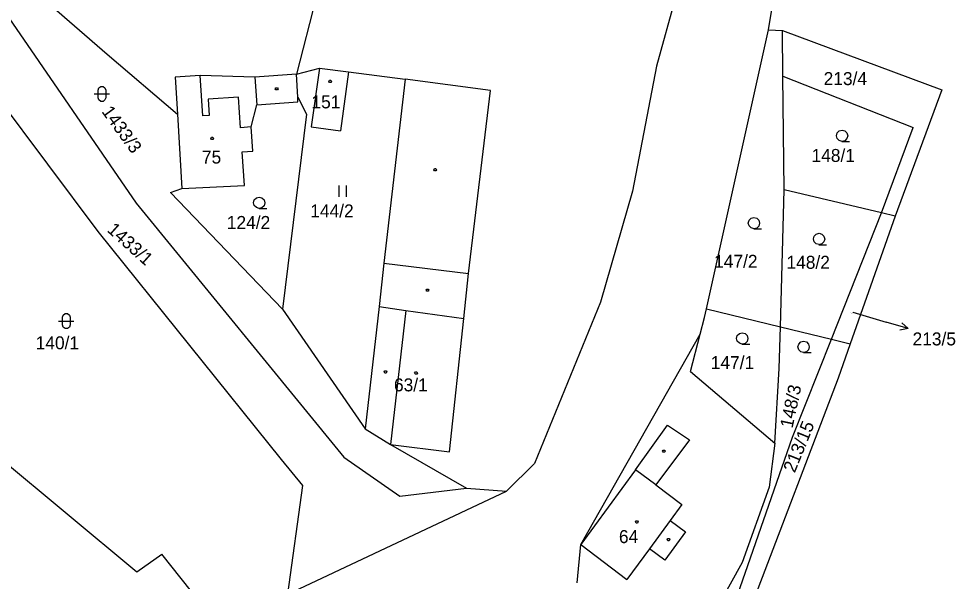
# Model space of a CAD drawing. Extents: x -852001 to -842497, y -1063614 to -1052182.
# Drawn here: x -849124.2 to -849001.5, y -1056168.6 to -1056094.9 of the extents above; entities that cross this region are included whole.
import ezdxf

# ---------------------------------------------------------------- set-up
doc = ezdxf.new("R2010")
doc.units = 0
for name, color, linetype in [('Default', 7, 'Continuous'), ('KN_HRANICE', 7, 'Continuous'), ('KN_KULTURY', 7, 'Continuous'), ('KN_PARCELY', 7, 'Continuous'), ('KN_SLUCKY', 7, 'Continuous')]:
    doc.layers.add(name, color=color, linetype=linetype)

# ---------------------------------------------------------------- blocks, each defined once
blk = doc.blocks.new('304')
at = {"layer": 'Default'}
blk.add_lwpolyline([(0, 0), (-0.38, 0.1), (-0.65, 0.37), (-0.75, 0.74), (-0.65, 1.11), (-0.38, 1.38), (-0.01, 1.48), (0.36, 1.38), (0.63, 1.11), (0.73, 0.73), (0.63, 0.35), (0.36, 0.08), (-0.02, -0.02), (0.98, -0.02)], dxfattribs=at)
blk = doc.blocks.new('306')
at = {"layer": 'Default'}
for p, q in [((-0.5, 1.5), (-0.5, 0)), ((0.5, 0), (0.5, 1.5))]:
    blk.add_line(p, q, dxfattribs=at)
blk = doc.blocks.new('316')
at = {"layer": 'Default'}
for points in [[(-0.5, 1.5), (-0.4, 1.79), (-0.15, 1.97), (0.16, 1.97), (0.41, 1.79), (0.51, 1.5), (0.51, 0.5), (0.41, 0.21), (0.16, 0.03), (-0.15, 0.03), (-0.4, 0.21), (-0.5, 0.5), (-0.5, 1.5)], [(-1, 1), (0.27, 1), (1, 1)]]:
    blk.add_lwpolyline(points, dxfattribs=at)
blk = doc.blocks.new('10292')
at = {"layer": 'Default'}
blk.add_line((0, 3), (0, 0), dxfattribs=at)
blk.add_lwpolyline([(-0.5, 2), (0, 3), (0.5, 2)], dxfattribs=at)
blk = doc.blocks.new('402')
at = {"layer": 'Default'}
blk.add_lwpolyline([(0.09, 0.15), (0.18, 0), (0.09, -0.15), (-0.09, -0.15), (-0.18, 0), (-0.09, 0.15), (0.09, 0.15)], dxfattribs=at)

msp = doc.modelspace()

# ---------------------------------------------------------------- linework, layer by layer
at = {"layer": 'KN_HRANICE'}
for p, q in [((-849061.59, -1055999.43), (-849087.8, -1056102.18)), ((-849061.59, -1055999.43), (-849087.8, -1056102.18)), ((-849026.02, -1056048.69), (-849040.65, -1056101.15)), ((-849026.02, -1056048.69), (-849040.65, -1056101.15)), ((-849025.96, -1056096.38), (-849019.75, -1056059.38)), ((-849025.96, -1056096.38), (-849019.75, -1056059.38)), ((-849120.52, -1056092.73), (-849112.59, -1056099.57)), ((-849120.52, -1056092.73), (-849112.59, -1056099.57)), ((-849125.98, -1056094.1), (-849108.8, -1056119.1)), ((-849125.98, -1056094.1), (-849108.8, -1056119.1)), ((-849113.79, -1056122.8), (-849134.65, -1056094.95)), ((-849113.79, -1056122.8), (-849134.65, -1056094.95)), ((-849034.09, -1056132.93), (-849025.96, -1056096.38)), ((-849034.09, -1056132.93), (-849025.96, -1056096.38)), ((-849025.96, -1056096.38), (-849024.15, -1056096.47)), ((-849025.96, -1056096.38), (-849024.15, -1056096.47)), ((-849024.15, -1056096.47), (-849003.24, -1056104.25)), ((-849024.08, -1056102.46), (-849024.15, -1056096.47)), ((-849024.15, -1056096.47), (-849003.24, -1056104.25)), ((-849024.08, -1056102.46), (-849024.15, -1056096.47)), ((-849112.59, -1056099.57), (-849103.4, -1056107.43)), ((-849112.59, -1056099.57), (-849103.4, -1056107.43)), ((-849087.8, -1056102.18), (-849084.8, -1056101.39)), ((-849087.8, -1056102.18), (-849084.8, -1056101.39)), ((-849084.8, -1056101.39), (-849085.87, -1056109.07)), ((-849084.8, -1056101.39), (-849085.87, -1056109.07)), ((-849084.8, -1056101.39), (-849081, -1056101.88)), ((-849084.8, -1056101.39), (-849081, -1056101.88)), ((-849040.65, -1056101.15), (-849043.77, -1056117.52)), ((-849040.65, -1056101.15), (-849043.77, -1056117.52)), ((-849100.4, -1056102.37), (-849103.68, -1056102.59)), ((-849100.4, -1056102.37), (-849103.68, -1056102.59)), ((-849103.68, -1056102.59), (-849103.4, -1056107.43)), ((-849103.68, -1056102.59), (-849103.4, -1056107.43)), ((-849093.28, -1056102.6), (-849100.4, -1056102.37)), ((-849093.28, -1056102.6), (-849100.4, -1056102.37)), ((-849087.8, -1056102.18), (-849093.28, -1056102.6)), ((-849087.8, -1056102.18), (-849093.28, -1056102.6)), ((-849087.64, -1056105.2), (-849087.8, -1056102.18)), ((-849087.64, -1056105.2), (-849087.8, -1056102.18)), ((-849081, -1056101.88), (-849082.02, -1056109.6)), ((-849081, -1056101.88), (-849082.02, -1056109.6)), ((-849081, -1056101.88), (-849073.57, -1056102.83)), ((-849081, -1056101.88), (-849073.57, -1056102.83)), ((-849073.57, -1056102.83), (-849076.34, -1056126.97)), ((-849073.57, -1056102.83), (-849076.34, -1056126.97)), ((-849062.38, -1056104.35), (-849073.57, -1056102.83)), ((-849062.38, -1056104.35), (-849073.57, -1056102.83)), ((-849024.08, -1056102.46), (-849007, -1056109.17)), ((-849023.9, -1056117.35), (-849024.08, -1056102.46)), ((-849024.08, -1056102.46), (-849007, -1056109.17)), ((-849023.9, -1056117.35), (-849024.08, -1056102.46)), ((-849087.61, -1056105.82), (-849087.64, -1056105.2)), ((-849087.64, -1056105.2), (-849086.51, -1056107.42)), ((-849087.61, -1056105.82), (-849087.64, -1056105.2)), ((-849087.64, -1056105.2), (-849086.51, -1056107.42)), ((-849065.26, -1056128.29), (-849062.38, -1056104.35)), ((-849065.26, -1056128.29), (-849062.38, -1056104.35)), ((-849003.24, -1056104.25), (-849009.36, -1056120.8)), ((-849003.24, -1056104.25), (-849009.36, -1056120.8)), ((-849093.72, -1056109.11), (-849092.99, -1056106.2)), ((-849093.72, -1056109.11), (-849092.99, -1056106.2)), ((-849092.99, -1056106.2), (-849087.61, -1056105.82)), ((-849092.99, -1056106.2), (-849087.61, -1056105.82)), ((-849103.4, -1056107.43), (-849102.84, -1056117.15)), ((-849103.4, -1056107.43), (-849102.84, -1056117.15)), ((-849086.51, -1056107.42), (-849089.63, -1056132.97)), ((-849086.51, -1056107.42), (-849089.63, -1056132.97)), ((-849093.51, -1056112.28), (-849093.72, -1056109.11)), ((-849093.51, -1056112.28), (-849093.72, -1056109.11)), ((-849085.87, -1056109.07), (-849082.02, -1056109.6)), ((-849085.87, -1056109.07), (-849082.02, -1056109.6)), ((-849011.17, -1056120.37), (-849007, -1056109.17)), ((-849011.17, -1056120.37), (-849007, -1056109.17)), ((-849094.92, -1056112.37), (-849093.51, -1056112.28)), ((-849094.92, -1056112.37), (-849093.51, -1056112.28)), ((-849094.63, -1056116.77), (-849094.92, -1056112.37)), ((-849094.63, -1056116.77), (-849094.92, -1056112.37)), ((-849104.3, -1056117.68), (-849102.84, -1056117.15)), ((-849104.3, -1056117.68), (-849102.84, -1056117.15)), ((-849102.84, -1056117.15), (-849094.63, -1056116.77)), ((-849102.84, -1056117.15), (-849094.63, -1056116.77)), ((-849043.77, -1056117.52), (-849047.99, -1056132.07)), ((-849043.77, -1056117.52), (-849047.99, -1056132.07)), ((-849024.4, -1056135.3), (-849023.9, -1056117.35)), ((-849024.4, -1056135.3), (-849023.9, -1056117.35)), ((-849011.17, -1056120.37), (-849023.9, -1056117.35)), ((-849011.17, -1056120.37), (-849023.9, -1056117.35)), ((-849104.3, -1056117.68), (-849089.63, -1056132.97)), ((-849104.3, -1056117.68), (-849089.63, -1056132.97)), ((-849108.8, -1056119.1), (-849081.6, -1056152.37)), ((-849108.8, -1056119.1), (-849081.6, -1056152.37)), ((-849017.73, -1056136.93), (-849011.17, -1056120.37)), ((-849017.73, -1056136.93), (-849011.17, -1056120.37)), ((-849009.36, -1056120.8), (-849015.25, -1056137.54)), ((-849009.36, -1056120.8), (-849015.25, -1056137.54)), ((-849009.36, -1056120.8), (-849011.17, -1056120.37)), ((-849009.36, -1056120.8), (-849011.17, -1056120.37)), ((-849089.76, -1056152.69), (-849113.79, -1056122.8)), ((-849089.76, -1056152.69), (-849113.79, -1056122.8)), ((-849076.34, -1056126.97), (-849076.99, -1056132.65)), ((-849076.34, -1056126.97), (-849076.99, -1056132.65)), ((-849065.89, -1056134.2), (-849065.26, -1056128.29)), ((-849065.89, -1056134.2), (-849065.26, -1056128.29)), ((-849047.99, -1056132.07), (-849056.6, -1056153.2)), ((-849047.99, -1056132.07), (-849056.6, -1056153.2)), ((-849089.63, -1056132.97), (-849078.82, -1056148.64)), ((-849089.63, -1056132.97), (-849078.82, -1056148.64)), ((-849076.99, -1056132.65), (-849078.82, -1056148.64)), ((-849076.99, -1056132.65), (-849078.82, -1056148.64)), ((-849034.34, -1056134.08), (-849034.09, -1056132.93)), ((-849034.34, -1056134.08), (-849034.09, -1056132.93)), ((-849034.09, -1056132.93), (-849024.4, -1056135.3)), ((-849034.09, -1056132.93), (-849024.4, -1056135.3)), ((-849067.76, -1056151.67), (-849065.89, -1056134.2)), ((-849067.76, -1056151.67), (-849065.89, -1056134.2)), ((-849034.91, -1056136.25), (-849034.34, -1056134.08)), ((-849034.91, -1056136.25), (-849034.34, -1056134.08)), ((-849024.55, -1056140.74), (-849024.4, -1056135.3)), ((-849024.55, -1056140.74), (-849024.4, -1056135.3)), ((-849024.4, -1056135.3), (-849017.73, -1056136.93)), ((-849024.4, -1056135.3), (-849017.73, -1056136.93)), ((-849050.56, -1056163.8), (-849034.91, -1056136.25)), ((-849050.56, -1056163.8), (-849034.91, -1056136.25)), ((-849036.2, -1056141.14), (-849034.91, -1056136.25)), ((-849036.2, -1056141.14), (-849034.91, -1056136.25)), ((-849022.82, -1056149.76), (-849017.73, -1056136.93)), ((-849022.82, -1056149.76), (-849017.73, -1056136.93)), ((-849017.73, -1056136.93), (-849015.25, -1056137.54)), ((-849017.73, -1056136.93), (-849015.25, -1056137.54)), ((-849015.25, -1056137.54), (-849016.83, -1056142.02)), ((-849015.25, -1056137.54), (-849016.83, -1056142.02)), ((-849025.13, -1056150.52), (-849024.55, -1056140.74)), ((-849025.13, -1056150.52), (-849024.55, -1056140.74)), ((-849036.2, -1056141.14), (-849025.13, -1056150.52)), ((-849036.2, -1056141.14), (-849025.13, -1056150.52)), ((-849016.83, -1056142.02), (-849029.93, -1056176.3)), ((-849016.83, -1056142.02), (-849029.93, -1056176.3)), ((-849136.05, -1056144.68), (-849108.72, -1056167.41)), ((-849136.05, -1056144.68), (-849108.72, -1056167.41)), ((-849078.82, -1056148.64), (-849075.49, -1056150.72)), ((-849078.82, -1056148.64), (-849075.49, -1056150.72)), ((-849033.29, -1056179.77), (-849022.82, -1056149.76)), ((-849033.29, -1056179.77), (-849022.82, -1056149.76)), ((-849025.13, -1056150.52), (-849025.89, -1056156.3)), ((-849025.13, -1056150.52), (-849025.89, -1056156.3)), ((-849075.49, -1056150.72), (-849065.52, -1056156.43)), ((-849075.49, -1056150.72), (-849067.76, -1056151.67)), ((-849075.49, -1056150.72), (-849065.52, -1056156.43)), ((-849075.49, -1056150.72), (-849067.76, -1056151.67)), ((-849086.95, -1056156.09), (-849089.76, -1056152.69)), ((-849086.95, -1056156.09), (-849089.76, -1056152.69)), ((-849081.6, -1056152.37), (-849074.26, -1056157.48)), ((-849081.6, -1056152.37), (-849074.26, -1056157.48)), ((-849060.28, -1056156.81), (-849056.6, -1056153.2)), ((-849060.28, -1056156.81), (-849056.6, -1056153.2)), ((-849088.95, -1056170.34), (-849086.95, -1056156.09)), ((-849088.95, -1056170.34), (-849086.95, -1056156.09)), ((-849088.95, -1056170.34), (-849060.28, -1056156.81)), ((-849088.95, -1056170.34), (-849060.28, -1056156.81)), ((-849074.26, -1056157.48), (-849065.52, -1056156.43)), ((-849074.26, -1056157.48), (-849065.52, -1056156.43)), ((-849065.52, -1056156.43), (-849060.28, -1056156.81)), ((-849065.52, -1056156.43), (-849060.28, -1056156.81)), ((-849025.89, -1056156.3), (-849029.4, -1056166.16)), ((-849025.89, -1056156.3), (-849029.4, -1056166.16)), ((-849051.02, -1056168.85), (-849050.56, -1056163.8)), ((-849051.02, -1056168.85), (-849050.56, -1056163.8)), ((-849108.72, -1056167.41), (-849105.46, -1056165.09)), ((-849108.72, -1056167.41), (-849105.46, -1056165.09)), ((-849097.52, -1056174.99), (-849105.46, -1056165.09)), ((-849097.52, -1056174.99), (-849105.46, -1056165.09)), ((-849029.4, -1056166.16), (-849034.13, -1056174.69)), ((-849029.4, -1056166.16), (-849034.13, -1056174.69))]:
    msp.add_line(p, q, dxfattribs=at)
at = {"layer": 'KN_PARCELY'}
msp.add_line((-849014.93, -1056133.38), (-849010.55, -1056134.67), dxfattribs=at)
msp.add_line((-849014.93, -1056133.38), (-849010.55, -1056134.67), dxfattribs=at)
at = {"layer": 'KN_SLUCKY'}
for p, q in [((-849100.05, -1056107.66), (-849100.4, -1056102.37)), ((-849100.05, -1056107.66), (-849100.4, -1056102.37)), ((-849093.28, -1056102.6), (-849092.99, -1056106.2)), ((-849093.28, -1056102.6), (-849092.99, -1056106.2)), ((-849095.4, -1056105.2), (-849099.36, -1056105.46)), ((-849095.4, -1056105.2), (-849099.36, -1056105.46)), ((-849095.14, -1056109.2), (-849095.4, -1056105.2)), ((-849095.14, -1056109.2), (-849095.4, -1056105.2)), ((-849099.36, -1056105.46), (-849099.22, -1056107.61)), ((-849099.36, -1056105.46), (-849099.22, -1056107.61)), ((-849099.22, -1056107.61), (-849100.05, -1056107.66)), ((-849099.22, -1056107.61), (-849100.05, -1056107.66)), ((-849093.72, -1056109.11), (-849095.14, -1056109.2)), ((-849093.72, -1056109.11), (-849095.14, -1056109.2)), ((-849076.34, -1056126.97), (-849065.26, -1056128.29)), ((-849076.34, -1056126.97), (-849065.26, -1056128.29)), ((-849076.99, -1056132.65), (-849073.47, -1056133.14)), ((-849076.99, -1056132.65), (-849073.47, -1056133.14)), ((-849073.47, -1056133.14), (-849075.49, -1056150.72)), ((-849073.47, -1056133.14), (-849075.49, -1056150.72)), ((-849073.47, -1056133.14), (-849065.89, -1056134.2)), ((-849073.47, -1056133.14), (-849065.89, -1056134.2)), ((-849043.39, -1056154.05), (-849039.2, -1056148.16)), ((-849043.39, -1056154.05), (-849039.2, -1056148.16)), ((-849039.2, -1056148.16), (-849036.32, -1056150.09)), ((-849039.2, -1056148.16), (-849036.32, -1056150.09)), ((-849036.32, -1056150.09), (-849040.74, -1056156.02)), ((-849036.32, -1056150.09), (-849040.74, -1056156.02)), ((-849043.39, -1056154.05), (-849050.56, -1056163.8)), ((-849043.39, -1056154.05), (-849050.56, -1056163.8)), ((-849040.74, -1056156.02), (-849043.39, -1056154.05)), ((-849040.74, -1056156.02), (-849043.39, -1056154.05)), ((-849040.74, -1056156.02), (-849037.3, -1056158.59)), ((-849040.74, -1056156.02), (-849037.3, -1056158.59)), ((-849037.3, -1056158.59), (-849038.84, -1056160.69)), ((-849037.3, -1056158.59), (-849038.84, -1056160.69)), ((-849038.84, -1056160.69), (-849041.55, -1056164.39)), ((-849038.84, -1056160.69), (-849041.55, -1056164.39)), ((-849038.84, -1056160.69), (-849036.85, -1056162.15)), ((-849038.84, -1056160.69), (-849036.85, -1056162.15)), ((-849036.85, -1056162.15), (-849039.56, -1056165.85)), ((-849036.85, -1056162.15), (-849039.56, -1056165.85)), ((-849050.56, -1056163.8), (-849044.51, -1056168.42)), ((-849050.56, -1056163.8), (-849044.51, -1056168.42)), ((-849041.55, -1056164.39), (-849044.51, -1056168.42)), ((-849041.55, -1056164.39), (-849044.51, -1056168.42)), ((-849039.56, -1056165.85), (-849041.55, -1056164.39)), ((-849039.56, -1056165.85), (-849041.55, -1056164.39))]:
    msp.add_line(p, q, dxfattribs=at)

# ---------------------------------------------------------------- block references
at = {"layer": 'KN_KULTURY'}
for name, p in [('316', (-849113.3, -1056105.78)), ('316', (-849113.3, -1056105.78)), ('402', (-849090.4, -1056104.11)), ('402', (-849090.4, -1056104.11)), ('402', (-849083.38, -1056103.13)), ('402', (-849083.38, -1056103.13)), ('304', (-849016.32, -1056110.99)), ('304', (-849016.32, -1056110.99)), ('402', (-849098.85, -1056110.61)), ('402', (-849098.85, -1056110.61)), ('402', (-849069.62, -1056114.71)), ('402', (-849069.62, -1056114.71)), ('306', (-849081.75, -1056118.26)), ('306', (-849081.75, -1056118.26)), ('304', (-849092.68, -1056119.77)), ('304', (-849092.68, -1056119.77)), ('304', (-849027.86, -1056122.44)), ('304', (-849027.86, -1056122.44)), ('304', (-849019.33, -1056124.52)), ('304', (-849019.33, -1056124.52)), ('402', (-849070.65, -1056130.49)), ('402', (-849070.65, -1056130.49)), ('316', (-849117.96, -1056135.54)), ('316', (-849117.96, -1056135.54)), ('304', (-849029.4, -1056137.55)), ('304', (-849029.4, -1056137.55)), ('304', (-849021.36, -1056138.66)), ('304', (-849021.36, -1056138.66)), ('402', (-849076.13, -1056141.21)), ('402', (-849076.13, -1056141.21)), ('402', (-849072.14, -1056141.35)), ('402', (-849072.14, -1056141.35)), ('402', (-849039.66, -1056151.59)), ('402', (-849039.66, -1056151.59)), ('402', (-849043.21, -1056160.85)), ('402', (-849043.21, -1056160.85)), ('402', (-849039.05, -1056163.18)), ('402', (-849039.05, -1056163.18))]:
    msp.add_blockref(name, p, dxfattribs=at)
at = {"layer": 'KN_PARCELY', "rotation": -106.466176}
msp.add_blockref('10292', (-849010.55, -1056134.67), dxfattribs=at)
msp.add_blockref('10292', (-849010.55, -1056134.67), dxfattribs=at)

# ---------------------------------------------------------------- texts
at = {"layer": 'KN_PARCELY'}
for s, height, p in [('213/4', 1.7, (-849018.74, -1056103.62)), ('213/4', 1.7, (-849018.74, -1056103.62)), ('151', 1.7, (-849085.84, -1056106.67)), ('151', 1.7, (-849085.84, -1056106.67)), ('75', 1.7, (-849100.19, -1056113.9)), ('75', 1.7, (-849100.19, -1056113.9)), ('148/1', 1.7, (-849020.33, -1056113.69)), ('148/1', 1.7, (-849020.33, -1056113.69)), ('144/2', 1.7, (-849086, -1056120.96)), ('144/2', 1.7, (-849086, -1056120.96)), ('124/2', 1.7, (-849096.93, -1056122.47)), ('124/2', 1.7, (-849096.93, -1056122.47)), ('147/2', 1.7, (-849033.09, -1056127.56)), ('147/2', 1.7, (-849033.09, -1056127.56)), ('148/2', 1.7, (-849023.61, -1056127.69)), ('148/2', 1.7, (-849023.61, -1056127.69)), ('213/5', 0.1, (-849015.26, -1056133.56)), ('213/5', 0.1, (-849015.26, -1056133.56)), ('213/5', 1.7, (-849007.09, -1056137.73)), ('213/5', 1.7, (-849007.09, -1056137.73)), ('140/1', 1.7, (-849121.97, -1056138.24)), ('140/1', 1.7, (-849121.97, -1056138.24)), ('147/1', 1.7, (-849033.53, -1056140.83)), ('147/1', 1.7, (-849033.53, -1056140.83)), ('63/1', 1.7, (-849075.03, -1056143.75)), ('63/1', 1.7, (-849075.03, -1056143.75)), ('64', 1.7, (-849045.56, -1056163.63)), ('64', 1.7, (-849045.56, -1056163.63))]:
    msp.add_text(s, height=height, dxfattribs=at).set_placement(p)
for s, rotation, p in [('1433/3', 305.902, (-849113.4, -1056107.09)), ('1433/3', 305.902, (-849113.4, -1056107.09)), ('1433/1', 317.992, (-849112.72, -1056122.73)), ('1433/1', 317.992, (-849112.72, -1056122.73)), ('148/3', 78.037, (-849022.82, -1056148.66)), ('148/3', 78.037, (-849022.82, -1056148.66)), ('213/15', 67.838, (-849022.53, -1056154.52)), ('213/15', 67.838, (-849022.53, -1056154.52))]:
    msp.add_text(s, height=1.7, rotation=rotation, dxfattribs=at).set_placement(p)

doc.saveas('drawing.dxf')
